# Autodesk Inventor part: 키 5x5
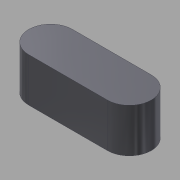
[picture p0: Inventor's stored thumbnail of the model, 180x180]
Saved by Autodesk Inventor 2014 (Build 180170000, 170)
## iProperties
Created: 2014-10
Part Number: 키 5x5
Document SubType Name: Modeling
Designer: KYOUNG IL JANG
Density: 7.86 g/cm^3
Mass: 2.54015 g
Surface Area: 2.9781 cm^2
Volume: 0.323175 cm^3
Material: 강철, 연강
Appearance: 강철 - 광택
d0: 5.000 mm
d1: 14.000 mm
d2: 5.000 mm
d3: 0.00 deg
Author: SeoGD™ [www.esajin.kr]
Revision Number: 1
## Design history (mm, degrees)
sketch "스케치1"
  geometry: L1 (-4.5, -2.5)-(4.5, -2.5); L2 (4.5, 2.5)-(-4.5, 2.5); A1 r 2.5 centre (4.5, 0) between (4.5, -2.5) and (4.5, 2.5); A2 r 2.5 centre (-4.5, 0) between (-4.5, 2.5) and (-4.5, -2.5); 2 further points
  constraints: 4 end point, 4 point on circle, 4 tangent, 2 centre point, 1 horizontal, 1 horizontal alignment, 1 midpoint, 1 parallel, 1 vertical alignment
  dimensions: "d0" = 5 distance between parallel lines of L1 L2; "d1" = 14 dimension on A1 A2
extrude "돌출1" new body sketch "스케치1" stored distance "d2" = 5; taper "d3" = 0 deg
node "솔리드1"
